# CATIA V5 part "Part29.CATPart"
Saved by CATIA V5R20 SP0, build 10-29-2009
Part number: 9TS2008M8
Revision: ANY
Definition: UNKNOWN
Nomenclature: 9TS2008M8
Source: Unknown
Bounding box of the stored display mesh (mm): x -10 to 10, y -10 to 10, z 0 to 8
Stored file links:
  C:\Users\Utente\Desktop\IO LAVORO\3D X SITO CF\CUMSA\3D files GR\GR 424546-10\Part29.CATPart
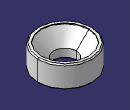
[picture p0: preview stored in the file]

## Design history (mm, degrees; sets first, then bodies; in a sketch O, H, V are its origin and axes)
Body1 "Chaflán1" (main body)
  Solid1: solid without history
